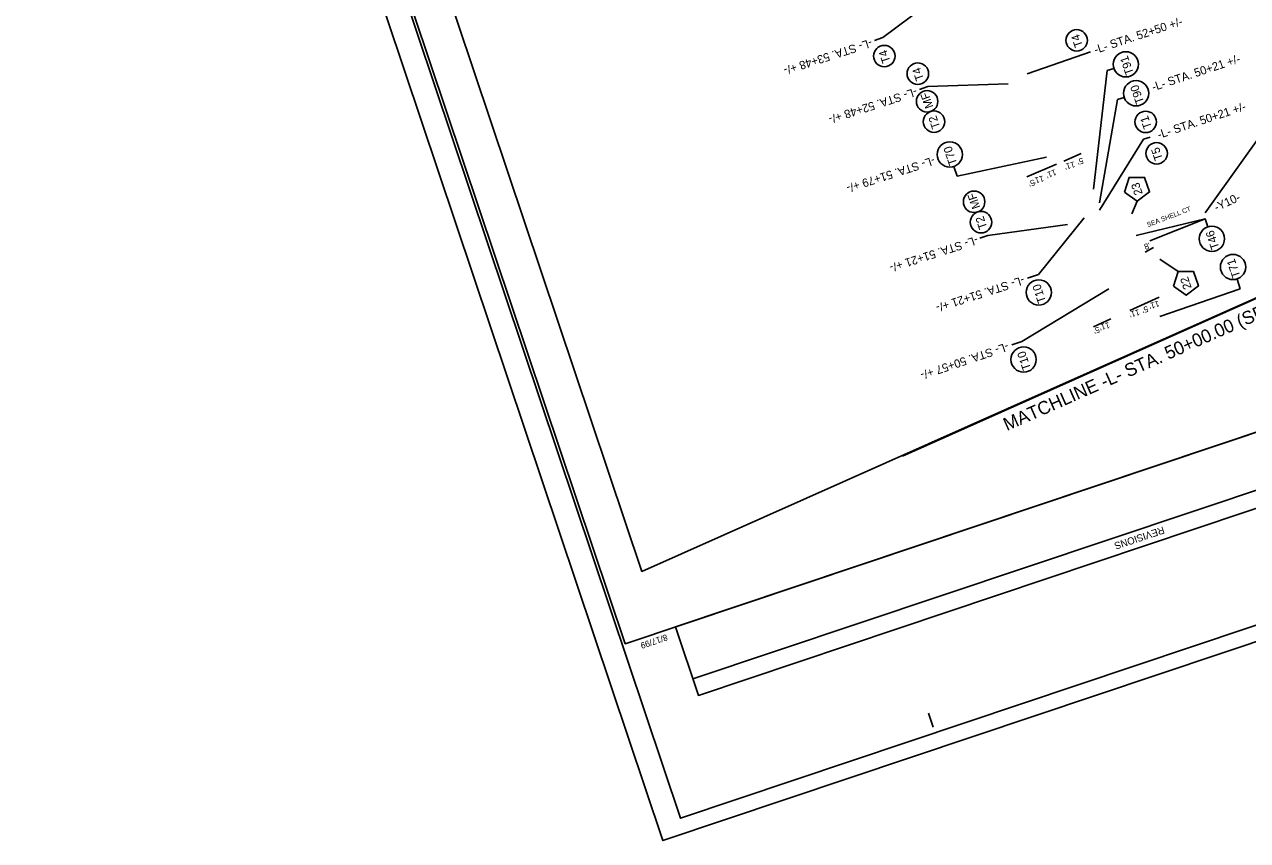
# Model space of a CAD drawing. Extents: x 1615436 to 1617119, y 903110 to 905145.
# Drawn here: x 1615436 to 1616462, y 903110 to 903795 of the extents above; entities that cross this region are included whole.
import ezdxf

# ---------------------------------------------------------------- set-up
doc = ezdxf.new("R2010")
doc.units = 0
for name, color, linetype in [('Default', 7, 'Continuous'), ('Matchline', 7, 'Continuous'), ('Matchline Text', 7, 'Continuous'), ('Prop Horizontal Alignment Curve and Spiral Data', 7, 'Continuous'), ('Prop Horizontal Alignment Tick Label', 7, 'Continuous'), ('Sheet Block Revision CELL', 7, 'Continuous'), ('Sheet Layout Plan Border', 7, 'Continuous'), ('Sheet Plan CELL', 7, 'Continuous'), ('Sheet Plot Border Inside CELL', 7, 'Continuous'), ('Sheet Plot Border Outside CELL', 7, 'Continuous'), ('Text', 7, 'Continuous')]:
    doc.layers.add(name, color=color, linetype=linetype)

msp = doc.modelspace()

# ---------------------------------------------------------------- linework, layer by layer
at = {"layer": 'Matchline'}
msp.add_line((1616172.6, 903432.8), (1616672.6, 903656.2), dxfattribs=at)
at = {"layer": 'Prop Horizontal Alignment Curve and Spiral Data'}
msp.add_line((1616509.8, 903753.8), (1616426.4, 903636.9), dxfattribs=at)
at = {"layer": 'Sheet Block Revision CELL'}
msp.add_line((1616746.5, 903497.4), (1615996.9, 903246), dxfattribs=at)
msp.add_lwpolyline([(1616751.1, 903483.7), (1616001.5, 903232.2), (1615982.2, 903289.6), (1616731.8, 903541)], close=True, dxfattribs=at)
at = {"layer": 'Sheet Layout Plan Border'}
msp.add_lwpolyline([(1616672.6, 903656.2), (1616919.8, 903656.8), (1616590.6, 904611.2), (1616386.8, 904624.4), (1616334.8, 904821.6), (1616466, 905009.6), (1615641.1, 904732.9), (1615700, 904557.2), (1615560.3, 904510.3), (1615954.2, 903336.2)], close=True, dxfattribs=at)
at = {"layer": 'Sheet Plan CELL'}
for p, q in [((1615940.2, 903275.5), (1615940.2, 903275.5)), ((1616198.4, 903205.5), (1616194.4, 903217.3))]:
    msp.add_line(p, q, dxfattribs=at)
msp.add_lwpolyline([(1615463.1, 904697.6), (1615940.2, 903275.5), (1616935.7, 903609.4), (1616458.6, 905031.5)], close=True, dxfattribs=at)
at = {"layer": 'Sheet Plot Border Inside CELL'}
msp.add_lwpolyline([(1616986.9, 903464.7), (1616457, 905044.2), (1615456.8, 904708.7), (1615986.6, 903129.2)], close=True, dxfattribs=at)
at = {"layer": 'Sheet Plot Border Outside CELL'}
msp.add_lwpolyline([(1617010, 903458.7), (1616474.6, 905054.8), (1615436.4, 904706.6), (1615971.8, 903110.5)], close=True, dxfattribs=at)
at = {"layer": 'Text'}
for p, q in [((1616227.4, 903837.2), (1616156.1, 903784)), ((1616156.1, 903784), (1616149.1, 903781.5)), ((1616277.3, 903753.6), (1616324.7, 903770)), ((1616330.2, 903771.9), (1616324.7, 903770)), ((1616332.7, 903656.9), (1616344.3, 903756.3)), ((1616344.3, 903756.3), (1616349.9, 903758.1)), ((1616193.8, 903743), (1616186.8, 903740.5)), ((1616261.3, 903745.1), (1616193.8, 903743)), ((1616337.7, 903645.3), (1616353, 903732)), ((1616353, 903732), (1616358.5, 903733.8)), ((1616337.8, 903639.2), (1616374.8, 903698.7)), ((1616374.8, 903698.7), (1616380.4, 903700.5)), ((1616307.8, 903680.3), (1616322.5, 903686.6)), ((1616218.4, 903667.6), (1616215.6, 903675.9)), ((1616293.3, 903683.6), (1616218.4, 903667.6)), ((1616277, 903667.1), (1616301.8, 903677.8)), ((1616369.4, 903646.8), (1616365, 903636.1)), ((1616311.1, 903627.2), (1616244.3, 903618)), ((1616325.1, 903632.7), (1616286.7, 903585.2)), ((1616368.7, 903618), (1616426.3, 903632)), ((1616379.9, 903613.4), (1616426.3, 903632)), ((1616426.3, 903632), (1616428.7, 903625.3)), ((1616244.3, 903618), (1616237.5, 903615.7)), ((1616383, 903607.9), (1616376, 903604)), ((1616403.7, 903587.6), (1616388.4, 903598)), ((1616277.6, 903582.2), (1616286.7, 903585.2)), ((1616345.6, 903573.3), (1616272.7, 903528.9)), ((1616388.5, 903550), (1616455.9, 903573.2)), ((1616455.9, 903573.2), (1616453.2, 903581.4)), ((1616363.4, 903555.1), (1616388, 903566.1)), ((1616332.8, 903541.4), (1616347.4, 903547.9)), ((1616272.7, 903528.9), (1616264.4, 903526.1))]:
    msp.add_line(p, q, dxfattribs=at)
for points in [[(1616358.9, 903654.3), (1616369.4, 903646.8), (1616379.8, 903654.5), (1616375.6, 903666.7), (1616362.7, 903666.6)], [(1616399.9, 903575.3), (1616410.4, 903567.8), (1616420.8, 903575.6), (1616416.6, 903587.8), (1616403.7, 903587.6)]]:
    msp.add_lwpolyline(points, close=True, dxfattribs=at)
for centre, radius in [((1616318.7, 903781.6), 9.01), ((1616157.4, 903768.4), 9.01), ((1616359.9, 903761.5), 10.6), ((1616185.5, 903753.7), 9.01), ((1616368.5, 903737.2), 10.6), ((1616193.3, 903730.4), 9.01), ((1616199.1, 903713.4), 9.01), ((1616376.6, 903713.2), 9.01), ((1616212.3, 903685.9), 10.6), ((1616385.7, 903686.8), 9.01), ((1616232.7, 903646.2), 9.01), ((1616238.5, 903629.1), 9.01), ((1616432.1, 903615.2), 10.6), ((1616449.8, 903591.5), 10.6), ((1616286.9, 903570.2), 10.6), ((1616274.2, 903513.9), 10.6)]:
    msp.add_circle(centre, radius, dxfattribs=at)

# ---------------------------------------------------------------- texts
at = {"layer": 'Default'}
msp.add_text('SEA SHELL CT', height=4, rotation=20.7477, dxfattribs=at).set_placement((1616378.4, 903624.9))
at = {"layer": 'Matchline Text'}
msp.add_text('MATCHLINE -L- STA. 50+00.00 (SEE SHEET PMP-5)', height=11, rotation=23.8606, dxfattribs=at).set_placement((1616260.2, 903453.8))
at = {"layer": 'Prop Horizontal Alignment Tick Label'}
msp.add_text('-Y10-', height=7, rotation=24.7508, dxfattribs=at).set_placement((1616435.9, 903638))
at = {"layer": 'Sheet Block Revision CELL'}
msp.add_text('REVISIONS', height=6, rotation=198.5432, dxfattribs=at).set_placement((1616391.1, 903374))
at = {"layer": 'Sheet Plan CELL'}
msp.add_text('8/17/99', height=5.25, rotation=198.5432, dxfattribs=at).set_placement((1615974.6, 903283.6))
at = {"layer": 'Text'}
for s, height, rotation, p in [('-L- STA. 52+50 +/-', 7, 18.3607, (1616334.6, 903770.2)), ('-L- STA. 53+48 +/-', 7, 197.8667, (1616146, 903783)), ('T4', 7, 108.5124, (1616324, 903777)), ('T4', 7, 108.5124, (1616162.7, 903763.8)), ('T91', 7, 109.1388, (1616366.7, 903754)), ('-L- STA. 50+21 +/-', 7, 18.3607, (1616383, 903738.9)), ('T4', 7, 108.5124, (1616190.8, 903749.1)), ('-L- STA. 52+48 +/-', 7, 197.8667, (1616183.7, 903742)), ('MF', 7, 109.1388, (1616198.6, 903725.9)), ('T90', 7, 109.1388, (1616375.3, 903729.7)), ('-L- STA. 50+21 +/-', 7, 18.3607, (1616387.7, 903698.9)), ('T2', 7, 108.5124, (1616204.3, 903708.7)), ('T1', 7, 108.5124, (1616381.8, 903708.6)), ('T70', 7, 108.5432, (1616218.6, 903678.2)), ('T5', 7, 108.5124, (1616391, 903682.2)), ('-L- STA. 51+79 +/-', 7, 197.8667, (1616198.7, 903684.3)), ("11'", 5, 195.4638, (1616316.5, 903680.1)), ("5'", 5, 195.4638, (1616323.6, 903683.3)), ("5'", 5, 195.4638, (1616282.7, 903665)), ("11'", 5, 195.4638, (1616290.4, 903668.3)), ("11'", 5, 201.3369, (1616300.5, 903673.6)), ('23', 7, 108.5124, (1616374.1, 903653.1)), ('MF', 7, 109.1388, (1616238, 903641.6)), ('T2', 7, 108.5124, (1616243.8, 903624.5)), ('-L- STA. 51+21 +/-', 7, 197.8667, (1616234.8, 903617.6)), ('T46', 7, 108.5432, (1616438.4, 903607.6)), ("8'", 5, 21.4628, (1616376.5, 903605.7)), ('T71', 7, 108.5432, (1616456.1, 903583.8)), ('-L- STA. 51+21 +/-', 7, 197.8667, (1616273.7, 903584)), ('22', 7, 108.5124, (1616415.2, 903574.1)), ('T10', 7, 108.5432, (1616293.1, 903562.6)), ("11'", 5, 195.4638, (1616387.2, 903563.3)), ("11'", 5, 195.4638, (1616370.8, 903556.2)), ("5'", 5, 195.4638, (1616377.9, 903558.9)), ("5'", 5, 195.4638, (1616337.2, 903541.6)), ("11'", 5, 195.4638, (1616345.7, 903545.4)), ('-L- STA. 50+57 +/-', 7, 198.5432, (1616260.4, 903528.3)), ('T10', 7, 108.5432, (1616280.4, 903506.3))]:
    msp.add_text(s, height=height, rotation=rotation, dxfattribs=at).set_placement(p)

doc.saveas('drawing.dxf')
